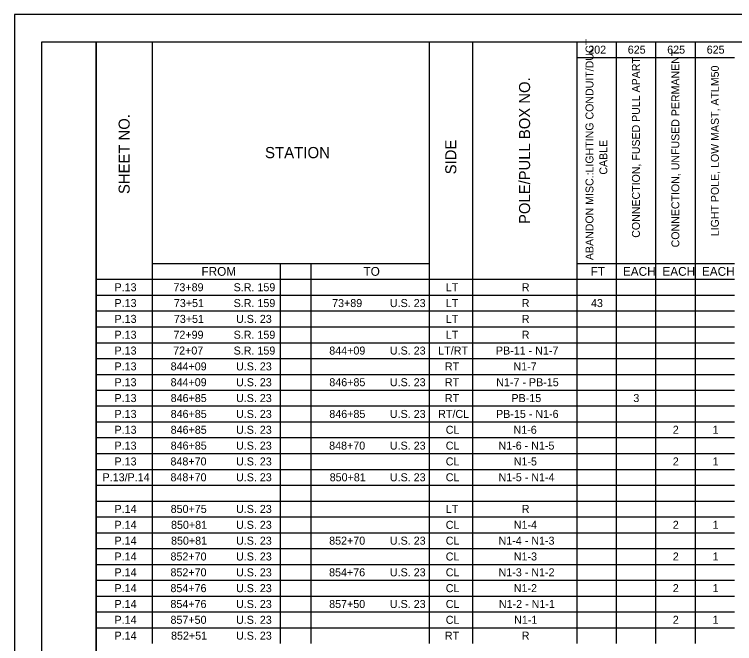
# Model space of a CAD drawing. Extents: x 0 to 34, y 0 to 22.
# Drawn here: x 0 to 13.2, y 10.47 to 22 of the extents above; entities that cross this region are included whole.
import ezdxf

# ---------------------------------------------------------------- set-up
doc = ezdxf.new("R2010")
doc.units = 0
for name, color, linetype in [('Default', 7, 'Continuous'), ('SH_Border', 7, 'Continuous'), ('SH_Cut_Line', 7, 'Continuous')]:
    doc.layers.add(name, color=color, linetype=linetype)

msp = doc.modelspace()

# ---------------------------------------------------------------- linework, layer by layer
at = {"layer": 'Default'}
for p, q in [((1.5, 21.5), (4.872, 21.5)), ((1.5, 21.5), (1.5, 21.21)), ((2.524, 21.5), (2.524, 21.21)), ((4.872, 21.5), (5.432, 21.5)), ((5.432, 21.5), (13.2, 21.5)), ((7.603, 21.5), (7.603, 21.21)), ((8.394, 21.5), (8.394, 21.21)), ((10.306, 21.5), (10.306, 21.21)), ((11.029, 21.5), (11.029, 21.21)), ((11.753, 21.5), (11.753, 21.21)), ((12.476, 21.5), (12.476, 21.21)), ((1.5, 21.21), (1.5, 20.92)), ((2.524, 21.21), (2.524, 20.92)), ((7.603, 21.21), (7.603, 20.92)), ((8.394, 21.21), (8.394, 20.92)), ((10.306, 21.21), (13.2, 21.21)), ((10.306, 21.21), (10.306, 20.92)), ((11.029, 21.21), (11.029, 20.92)), ((11.753, 21.21), (11.753, 20.92)), ((12.476, 21.21), (12.476, 20.92)), ((1.5, 20.92), (1.5, 20.63)), ((2.524, 20.92), (2.524, 20.63)), ((7.603, 20.92), (7.603, 20.63)), ((8.394, 20.92), (8.394, 20.63)), ((10.306, 20.92), (10.306, 20.63)), ((11.029, 20.92), (11.029, 20.63)), ((11.753, 20.92), (11.753, 20.63)), ((12.476, 20.92), (12.476, 20.63)), ((1.5, 20.63), (1.5, 20.339)), ((2.524, 20.63), (2.524, 20.339)), ((7.603, 20.63), (7.603, 20.339)), ((8.394, 20.63), (8.394, 20.339)), ((10.306, 20.63), (10.306, 20.339)), ((11.029, 20.63), (11.029, 20.339)), ((11.753, 20.63), (11.753, 20.339)), ((12.476, 20.63), (12.476, 20.339)), ((1.5, 20.339), (1.5, 20.049)), ((2.524, 20.339), (2.524, 20.049)), ((7.603, 20.339), (7.603, 20.049)), ((8.394, 20.339), (8.394, 20.049)), ((10.306, 20.339), (10.306, 20.049)), ((11.029, 20.339), (11.029, 20.049)), ((11.753, 20.339), (11.753, 20.049)), ((12.476, 20.339), (12.476, 20.049)), ((1.5, 20.049), (1.5, 19.759)), ((2.524, 20.049), (2.524, 19.759)), ((7.603, 20.049), (7.603, 19.759)), ((8.394, 20.049), (8.394, 19.759)), ((10.306, 20.049), (10.306, 19.759)), ((11.029, 20.049), (11.029, 19.759)), ((11.753, 20.049), (11.753, 19.759)), ((12.476, 20.049), (12.476, 19.759)), ((1.5, 19.759), (1.5, 19.469)), ((2.524, 19.759), (2.524, 19.469)), ((7.603, 19.759), (7.603, 19.469)), ((8.394, 19.759), (8.394, 19.469)), ((10.306, 19.759), (10.306, 19.469)), ((11.029, 19.759), (11.029, 19.469)), ((11.753, 19.759), (11.753, 19.469)), ((12.476, 19.759), (12.476, 19.469)), ((1.5, 19.469), (1.5, 19.179)), ((2.524, 19.469), (2.524, 19.179)), ((7.603, 19.469), (7.603, 19.179)), ((8.394, 19.469), (8.394, 19.179)), ((10.306, 19.469), (10.306, 19.179)), ((11.029, 19.469), (11.029, 19.179)), ((11.753, 19.469), (11.753, 19.179)), ((12.476, 19.469), (12.476, 19.179)), ((1.5, 19.179), (1.5, 18.889)), ((2.524, 19.179), (2.524, 18.889)), ((7.603, 19.179), (7.603, 18.889)), ((8.394, 19.179), (8.394, 18.889)), ((10.306, 19.179), (10.306, 18.889)), ((11.029, 19.179), (11.029, 18.889)), ((11.753, 19.179), (11.753, 18.889)), ((12.476, 19.179), (12.476, 18.889)), ((1.5, 18.889), (1.5, 18.599)), ((2.524, 18.889), (2.524, 18.599)), ((7.603, 18.889), (7.603, 18.599)), ((8.394, 18.889), (8.394, 18.599)), ((10.306, 18.889), (10.306, 18.599)), ((11.029, 18.889), (11.029, 18.599)), ((11.753, 18.889), (11.753, 18.599)), ((12.476, 18.889), (12.476, 18.599)), ((1.5, 18.599), (1.5, 18.308)), ((2.524, 18.599), (2.524, 18.308)), ((7.603, 18.599), (7.603, 18.308)), ((8.394, 18.599), (8.394, 18.308)), ((10.306, 18.599), (10.306, 18.308)), ((11.029, 18.599), (11.029, 18.308)), ((11.753, 18.599), (11.753, 18.308)), ((12.476, 18.599), (12.476, 18.308)), ((1.5, 18.308), (1.5, 18.018)), ((2.524, 18.308), (2.524, 18.018)), ((7.603, 18.308), (7.603, 18.018)), ((8.394, 18.308), (8.394, 18.018)), ((10.306, 18.308), (10.306, 18.018)), ((11.029, 18.308), (11.029, 18.018)), ((11.753, 18.308), (11.753, 18.018)), ((12.476, 18.308), (12.476, 18.018)), ((1.5, 18.018), (1.5, 17.728)), ((2.524, 18.018), (2.524, 17.728)), ((7.603, 18.018), (7.603, 17.728)), ((8.394, 18.018), (8.394, 17.728)), ((10.306, 18.018), (10.306, 17.728)), ((11.029, 18.018), (11.029, 17.728)), ((11.753, 18.018), (11.753, 17.728)), ((12.476, 18.018), (12.476, 17.728)), ((1.5, 17.728), (1.5, 17.438)), ((2.524, 17.728), (2.524, 17.438)), ((7.603, 17.728), (7.603, 17.438)), ((8.394, 17.728), (8.394, 17.438)), ((10.306, 17.728), (10.306, 17.438)), ((11.029, 17.728), (11.029, 17.438)), ((11.753, 17.728), (11.753, 17.438)), ((12.476, 17.728), (12.476, 17.438)), ((1.5, 17.438), (1.5, 17.148)), ((2.524, 17.438), (4.872, 17.438)), ((2.524, 17.438), (2.524, 17.148)), ((4.872, 17.438), (5.432, 17.438)), ((4.872, 17.438), (4.872, 17.148)), ((5.432, 17.438), (7.603, 17.438)), ((5.432, 17.438), (5.432, 17.148)), ((7.603, 17.438), (7.603, 17.148)), ((8.394, 17.438), (8.394, 17.148)), ((10.306, 17.438), (13.2, 17.438)), ((10.306, 17.438), (10.306, 17.148)), ((11.029, 17.438), (11.029, 17.148)), ((11.753, 17.438), (11.753, 17.148)), ((12.476, 17.438), (12.476, 17.148)), ((1.5, 17.148), (4.872, 17.148)), ((1.5, 17.148), (1.5, 16.858)), ((2.524, 17.148), (2.524, 16.858)), ((4.872, 17.148), (5.432, 17.148)), ((4.872, 17.148), (4.872, 16.858)), ((5.432, 17.148), (13.2, 17.148)), ((5.432, 17.148), (5.432, 16.858)), ((7.603, 17.148), (7.603, 16.858)), ((8.394, 17.148), (8.394, 16.858)), ((10.306, 17.148), (10.306, 16.858)), ((11.029, 17.148), (11.029, 16.858)), ((11.753, 17.148), (11.753, 16.858)), ((12.476, 17.148), (12.476, 16.858)), ((1.5, 16.858), (4.872, 16.858)), ((1.5, 16.858), (1.5, 16.568)), ((2.524, 16.858), (2.524, 16.568)), ((4.872, 16.858), (5.432, 16.858)), ((4.872, 16.858), (4.872, 16.568)), ((5.432, 16.858), (13.2, 16.858)), ((5.432, 16.858), (5.432, 16.568)), ((7.603, 16.858), (7.603, 16.568)), ((8.394, 16.858), (8.394, 16.568)), ((10.306, 16.858), (10.306, 16.568)), ((11.029, 16.858), (11.029, 16.568)), ((11.753, 16.858), (11.753, 16.568)), ((12.476, 16.858), (12.476, 16.568)), ((1.5, 16.568), (4.872, 16.568)), ((1.5, 16.568), (1.5, 16.278)), ((2.524, 16.568), (2.524, 16.278)), ((4.872, 16.568), (5.432, 16.568)), ((4.872, 16.568), (4.872, 16.278)), ((5.432, 16.568), (13.2, 16.568)), ((5.432, 16.568), (5.432, 16.278)), ((7.603, 16.568), (7.603, 16.278)), ((8.394, 16.568), (8.394, 16.278)), ((10.306, 16.568), (10.306, 16.278)), ((11.029, 16.568), (11.029, 16.278)), ((11.753, 16.568), (11.753, 16.278)), ((12.476, 16.568), (12.476, 16.278)), ((1.5, 16.278), (4.872, 16.278)), ((1.5, 16.278), (1.5, 15.987)), ((2.524, 16.278), (2.524, 15.987)), ((4.872, 16.278), (5.432, 16.278)), ((4.872, 16.278), (4.872, 15.987)), ((5.432, 16.278), (13.2, 16.278)), ((5.432, 16.278), (5.432, 15.987)), ((7.603, 16.278), (7.603, 15.987)), ((8.394, 16.278), (8.394, 15.987)), ((10.306, 16.278), (10.306, 15.987)), ((11.029, 16.278), (11.029, 15.987)), ((11.753, 16.278), (11.753, 15.987)), ((12.476, 16.278), (12.476, 15.987)), ((1.5, 15.987), (4.872, 15.987)), ((1.5, 15.987), (1.5, 15.697)), ((2.524, 15.987), (2.524, 15.697)), ((4.872, 15.987), (5.432, 15.987)), ((4.872, 15.987), (4.872, 15.697)), ((5.432, 15.987), (13.2, 15.987)), ((5.432, 15.987), (5.432, 15.697)), ((7.603, 15.987), (7.603, 15.697)), ((8.394, 15.987), (8.394, 15.697)), ((10.306, 15.987), (10.306, 15.697)), ((11.029, 15.987), (11.029, 15.697)), ((11.753, 15.987), (11.753, 15.697)), ((12.476, 15.987), (12.476, 15.697)), ((1.5, 15.697), (4.872, 15.697)), ((1.5, 15.697), (1.5, 15.407)), ((2.524, 15.697), (2.524, 15.407)), ((4.872, 15.697), (5.432, 15.697)), ((4.872, 15.697), (4.872, 15.407)), ((5.432, 15.697), (13.2, 15.697)), ((5.432, 15.697), (5.432, 15.407)), ((7.603, 15.697), (7.603, 15.407)), ((8.394, 15.697), (8.394, 15.407)), ((10.306, 15.697), (10.306, 15.407)), ((11.029, 15.697), (11.029, 15.407)), ((11.753, 15.697), (11.753, 15.407)), ((12.476, 15.697), (12.476, 15.407)), ((1.5, 15.407), (4.872, 15.407)), ((1.5, 15.407), (1.5, 15.117)), ((2.524, 15.407), (2.524, 15.117)), ((4.872, 15.407), (5.432, 15.407)), ((4.872, 15.407), (4.872, 15.117)), ((5.432, 15.407), (13.2, 15.407)), ((5.432, 15.407), (5.432, 15.117)), ((7.603, 15.407), (7.603, 15.117)), ((8.394, 15.407), (8.394, 15.117)), ((10.306, 15.407), (10.306, 15.117)), ((11.029, 15.407), (11.029, 15.117)), ((11.753, 15.407), (11.753, 15.117)), ((12.476, 15.407), (12.476, 15.117)), ((1.5, 15.117), (4.872, 15.117)), ((1.5, 15.117), (1.5, 14.827)), ((2.524, 15.117), (2.524, 14.827)), ((4.872, 15.117), (5.432, 15.117)), ((4.872, 15.117), (4.872, 14.827)), ((5.432, 15.117), (13.2, 15.117)), ((5.432, 15.117), (5.432, 14.827)), ((7.603, 15.117), (7.603, 14.827)), ((8.394, 15.117), (8.394, 14.827)), ((10.306, 15.117), (10.306, 14.827)), ((11.029, 15.117), (11.029, 14.827)), ((11.753, 15.117), (11.753, 14.827)), ((12.476, 15.117), (12.476, 14.827)), ((1.5, 14.827), (4.872, 14.827)), ((1.5, 14.827), (1.5, 14.537)), ((2.524, 14.827), (2.524, 14.537)), ((4.872, 14.827), (5.432, 14.827)), ((4.872, 14.827), (4.872, 14.537)), ((5.432, 14.827), (13.2, 14.827)), ((5.432, 14.827), (5.432, 14.537)), ((7.603, 14.827), (7.603, 14.537)), ((8.394, 14.827), (8.394, 14.537)), ((10.306, 14.827), (10.306, 14.537)), ((11.029, 14.827), (11.029, 14.537)), ((11.753, 14.827), (11.753, 14.537)), ((12.476, 14.827), (12.476, 14.537)), ((1.5, 14.537), (4.872, 14.537)), ((1.5, 14.537), (1.5, 14.247)), ((2.524, 14.537), (2.524, 14.247)), ((4.872, 14.537), (5.432, 14.537)), ((4.872, 14.537), (4.872, 14.247)), ((5.432, 14.537), (13.2, 14.537)), ((5.432, 14.537), (5.432, 14.247)), ((7.603, 14.537), (7.603, 14.247)), ((8.394, 14.537), (8.394, 14.247)), ((10.306, 14.537), (10.306, 14.247)), ((11.029, 14.537), (11.029, 14.247)), ((11.753, 14.537), (11.753, 14.247)), ((12.476, 14.537), (12.476, 14.247)), ((1.5, 14.247), (4.872, 14.247)), ((1.5, 14.247), (1.5, 13.956)), ((2.524, 14.247), (2.524, 13.956)), ((4.872, 14.247), (5.432, 14.247)), ((4.872, 14.247), (4.872, 13.956)), ((5.432, 14.247), (13.2, 14.247)), ((5.432, 14.247), (5.432, 13.956)), ((7.603, 14.247), (7.603, 13.956)), ((8.394, 14.247), (8.394, 13.956)), ((10.306, 14.247), (10.306, 13.956)), ((11.029, 14.247), (11.029, 13.956)), ((11.753, 14.247), (11.753, 13.956)), ((12.476, 14.247), (12.476, 13.956)), ((1.5, 13.956), (4.872, 13.956)), ((1.5, 13.956), (1.5, 13.666)), ((2.524, 13.956), (2.524, 13.666)), ((4.872, 13.956), (5.432, 13.956)), ((4.872, 13.956), (4.872, 13.666)), ((5.432, 13.956), (13.2, 13.956)), ((5.432, 13.956), (5.432, 13.666)), ((7.603, 13.956), (7.603, 13.666)), ((8.394, 13.956), (8.394, 13.666)), ((10.306, 13.956), (10.306, 13.666)), ((11.029, 13.956), (11.029, 13.666)), ((11.753, 13.956), (11.753, 13.666)), ((12.476, 13.956), (12.476, 13.666)), ((1.5, 13.666), (4.872, 13.666)), ((1.5, 13.666), (1.5, 13.376)), ((2.524, 13.666), (2.524, 13.376)), ((4.872, 13.666), (5.432, 13.666)), ((4.872, 13.666), (4.872, 13.376)), ((5.432, 13.666), (13.2, 13.666)), ((5.432, 13.666), (5.432, 13.376)), ((7.603, 13.666), (7.603, 13.376)), ((8.394, 13.666), (8.394, 13.376)), ((10.306, 13.666), (10.306, 13.376)), ((11.029, 13.666), (11.029, 13.376)), ((11.753, 13.666), (11.753, 13.376)), ((12.476, 13.666), (12.476, 13.376)), ((1.5, 13.376), (4.872, 13.376)), ((1.5, 13.376), (1.5, 13.086)), ((2.524, 13.376), (2.524, 13.086)), ((4.872, 13.376), (5.432, 13.376)), ((4.872, 13.376), (4.872, 13.086)), ((5.432, 13.376), (13.2, 13.376)), ((5.432, 13.376), (5.432, 13.086)), ((7.603, 13.376), (7.603, 13.086)), ((8.394, 13.376), (8.394, 13.086)), ((10.306, 13.376), (10.306, 13.086)), ((11.029, 13.376), (11.029, 13.086)), ((11.753, 13.376), (11.753, 13.086)), ((12.476, 13.376), (12.476, 13.086)), ((1.5, 13.086), (4.872, 13.086)), ((1.5, 13.086), (1.5, 12.796)), ((2.524, 13.086), (2.524, 12.796)), ((4.872, 13.086), (5.432, 13.086)), ((4.872, 13.086), (4.872, 12.796)), ((5.432, 13.086), (13.2, 13.086)), ((5.432, 13.086), (5.432, 12.796)), ((7.603, 13.086), (7.603, 12.796)), ((8.394, 13.086), (8.394, 12.796)), ((10.306, 13.086), (10.306, 12.796)), ((11.029, 13.086), (11.029, 12.796)), ((11.753, 13.086), (11.753, 12.796)), ((12.476, 13.086), (12.476, 12.796)), ((1.5, 12.796), (4.872, 12.796)), ((1.5, 12.796), (1.5, 12.506)), ((2.524, 12.796), (2.524, 12.506)), ((4.872, 12.796), (5.432, 12.796)), ((4.872, 12.796), (4.872, 12.506)), ((5.432, 12.796), (13.2, 12.796)), ((5.432, 12.796), (5.432, 12.506)), ((7.603, 12.796), (7.603, 12.506)), ((8.394, 12.796), (8.394, 12.506)), ((10.306, 12.796), (10.306, 12.506)), ((11.029, 12.796), (11.029, 12.506)), ((11.753, 12.796), (11.753, 12.506)), ((12.476, 12.796), (12.476, 12.506)), ((1.5, 12.506), (4.872, 12.506)), ((1.5, 12.506), (1.5, 12.216)), ((2.524, 12.506), (2.524, 12.216)), ((4.872, 12.506), (5.432, 12.506)), ((4.872, 12.506), (4.872, 12.216)), ((5.432, 12.506), (13.2, 12.506)), ((5.432, 12.506), (5.432, 12.216)), ((7.603, 12.506), (7.603, 12.216)), ((8.394, 12.506), (8.394, 12.216)), ((10.306, 12.506), (10.306, 12.216)), ((11.029, 12.506), (11.029, 12.216)), ((11.753, 12.506), (11.753, 12.216)), ((12.476, 12.506), (12.476, 12.216)), ((1.5, 12.216), (4.872, 12.216)), ((1.5, 12.216), (1.5, 11.926)), ((2.524, 12.216), (2.524, 11.926)), ((4.872, 12.216), (5.432, 12.216)), ((4.872, 12.216), (4.872, 11.926)), ((5.432, 12.216), (13.2, 12.216)), ((5.432, 12.216), (5.432, 11.926)), ((7.603, 12.216), (7.603, 11.926)), ((8.394, 12.216), (8.394, 11.926)), ((10.306, 12.216), (10.306, 11.926)), ((11.029, 12.216), (11.029, 11.926)), ((11.753, 12.216), (11.753, 11.926)), ((12.476, 12.216), (12.476, 11.926)), ((1.5, 11.926), (4.872, 11.926)), ((1.5, 11.926), (1.5, 11.635)), ((2.524, 11.926), (2.524, 11.635)), ((4.872, 11.926), (5.432, 11.926)), ((4.872, 11.926), (4.872, 11.635)), ((5.432, 11.926), (13.2, 11.926)), ((5.432, 11.926), (5.432, 11.635)), ((7.603, 11.926), (7.603, 11.635)), ((8.394, 11.926), (8.394, 11.635)), ((10.306, 11.926), (10.306, 11.635)), ((11.029, 11.926), (11.029, 11.635)), ((11.753, 11.926), (11.753, 11.635)), ((12.476, 11.926), (12.476, 11.635)), ((1.5, 11.635), (4.872, 11.635)), ((1.5, 11.635), (1.5, 11.345)), ((2.524, 11.635), (2.524, 11.345)), ((4.872, 11.635), (5.432, 11.635)), ((4.872, 11.635), (4.872, 11.345)), ((5.432, 11.635), (13.2, 11.635)), ((5.432, 11.635), (5.432, 11.345)), ((7.603, 11.635), (7.603, 11.345)), ((8.394, 11.635), (8.394, 11.345)), ((10.306, 11.635), (10.306, 11.345)), ((11.029, 11.635), (11.029, 11.345)), ((11.753, 11.635), (11.753, 11.345)), ((12.476, 11.635), (12.476, 11.345)), ((1.5, 11.345), (4.872, 11.345)), ((1.5, 11.345), (1.5, 11.055)), ((2.524, 11.345), (2.524, 11.055)), ((4.872, 11.345), (5.432, 11.345)), ((4.872, 11.345), (4.872, 11.055)), ((5.432, 11.345), (13.2, 11.345)), ((5.432, 11.345), (5.432, 11.055)), ((7.603, 11.345), (7.603, 11.055)), ((8.394, 11.345), (8.394, 11.055)), ((10.306, 11.345), (10.306, 11.055)), ((11.029, 11.345), (11.029, 11.055)), ((11.753, 11.345), (11.753, 11.055)), ((12.476, 11.345), (12.476, 11.055)), ((1.5, 11.055), (4.872, 11.055)), ((1.5, 11.055), (1.5, 10.765)), ((2.524, 11.055), (2.524, 10.765)), ((4.872, 11.055), (5.432, 11.055)), ((4.872, 11.055), (4.872, 10.765)), ((5.432, 11.055), (13.2, 11.055)), ((5.432, 11.055), (5.432, 10.765)), ((7.603, 11.055), (7.603, 10.765)), ((8.394, 11.055), (8.394, 10.765)), ((10.306, 11.055), (10.306, 10.765)), ((11.029, 11.055), (11.029, 10.765)), ((11.753, 11.055), (11.753, 10.765)), ((12.476, 11.055), (12.476, 10.765)), ((1.5, 10.765), (4.872, 10.765)), ((1.5, 10.765), (1.5, 10.475)), ((2.524, 10.765), (2.524, 10.475)), ((4.872, 10.765), (5.432, 10.765)), ((4.872, 10.765), (4.872, 10.475)), ((5.432, 10.765), (13.2, 10.765)), ((5.432, 10.765), (5.432, 10.475)), ((7.603, 10.765), (7.603, 10.475)), ((8.394, 10.765), (8.394, 10.475)), ((10.306, 10.765), (10.306, 10.475)), ((11.029, 10.765), (11.029, 10.475)), ((11.753, 10.765), (11.753, 10.475)), ((12.476, 10.765), (12.476, 10.475))]:
    msp.add_line(p, q, dxfattribs=at)
at = {"layer": 'SH_Border'}
for points in [[(0.5, 21.5), (1.5, 21.5), (1.5, 0.5), (0.5, 0.5)], [(1.5, 21.5), (33.5, 21.5), (33.5, 0.5), (1.5, 0.5)]]:
    msp.add_lwpolyline(points, close=True, dxfattribs=at)
at = {"layer": 'SH_Cut_Line'}
msp.add_lwpolyline([(0, 0), (34, 0), (34, 22), (0, 22)], close=True, dxfattribs=at)

# ---------------------------------------------------------------- texts
at = {"layer": 'Default'}
for s, height, p in [('ABANDON MISC.:LIGHTING CONDUIT/DUCT ', 0.14506, (10.613, 17.499)), ('CONNECTION, UNFUSED PERMANENT', 0.14506, (12.187, 17.733)), ('CONNECTION, FUSED PULL APART', 0.14506, (11.464, 17.909)), ('LIGHT POLE, LOW MAST, ATLM50', 0.14506, (12.911, 17.937)), ('POLE/PULL BOX NO.', 0.20308, (9.452, 18.161)), ('SHEET NO.', 0.2031, (2.113, 18.71)), ('SIDE', 0.2031, (8.1, 19.071)), ('CABLE', 0.1451, (10.867, 19.065))]:
    msp.add_text(s, height=height, rotation=90, dxfattribs=at).set_placement(p)
for s, height, p in [('202', 0.1468, (10.518, 21.281)), ('625', 0.1468, (11.242, 21.281)), ('625', 0.1468, (11.965, 21.281)), ('625', 0.1468, (12.689, 21.281)), ('STATION', 0.2055, (4.593, 19.366)), ('FROM', 0.1615, (3.428, 17.212)), ('TO', 0.1615, (6.398, 17.212)), ('FT', 0.1615, (10.562, 17.212)), ('EACH', 0.1615, (11.153, 17.212)), ('EACH', 0.1615, (11.877, 17.212)), ('EACH', 0.1615, (12.601, 17.212)), ('P.13', 0.1468, (1.835, 16.929)), ('73+89', 0.1468, (2.915, 16.929)), ('S.R. 159', 0.1468, (4.018, 16.929)), ('LT', 0.1468, (7.907, 16.929)), ('R', 0.147, (9.299, 16.929)), ('P.13', 0.1468, (1.835, 16.639)), ('73+51', 0.1468, (2.923, 16.639)), ('S.R. 159', 0.1468, (4.018, 16.639)), ('73+89', 0.1468, (5.823, 16.639)), ('U.S. 23', 0.1468, (6.882, 16.639)), ('LT', 0.1468, (7.907, 16.639)), ('R', 0.147, (9.299, 16.639)), ('43', 0.1468, (10.568, 16.639)), ('P.13', 0.1468, (1.835, 16.349)), ('73+51', 0.1468, (2.923, 16.349)), ('U.S. 23', 0.1468, (4.062, 16.349)), ('LT', 0.1468, (7.907, 16.349)), ('R', 0.147, (9.299, 16.349)), ('P.13', 0.1468, (1.835, 16.059)), ('72+99', 0.1468, (2.915, 16.059)), ('S.R. 159', 0.1468, (4.018, 16.059)), ('LT', 0.1468, (7.907, 16.059)), ('R', 0.147, (9.299, 16.059)), ('P.13', 0.1468, (1.835, 15.769)), ('72+07', 0.1468, (2.91, 15.769)), ('S.R. 159', 0.1468, (4.018, 15.769)), ('844+09', 0.1468, (5.771, 15.769)), ('U.S. 23', 0.1468, (6.882, 15.769)), ('LT/RT', 0.1468, (7.768, 15.769)), ('PB-11 - N1-7', 0.14679, (8.825, 15.769)), ('P.13', 0.1468, (1.835, 15.479)), ('844+09', 0.1468, (2.863, 15.479)), ('U.S. 23', 0.1468, (4.062, 15.479)), ('RT', 0.1468, (7.89, 15.479)), ('N1-7', 0.1468, (9.146, 15.479)), ('P.13', 0.1468, (1.835, 15.189)), ('844+09', 0.1468, (2.863, 15.189)), ('U.S. 23', 0.1468, (4.062, 15.189)), ('846+85', 0.1468, (5.772, 15.189)), ('U.S. 23', 0.1468, (6.882, 15.189)), ('RT', 0.1468, (7.89, 15.189)), ('N1-7 - PB-15', 0.14679, (8.831, 15.189)), ('P.13', 0.1468, (1.835, 14.899)), ('846+85', 0.1468, (2.864, 14.899)), ('U.S. 23', 0.1468, (4.062, 14.899)), ('RT', 0.1468, (7.89, 14.899)), ('PB-15', 0.1468, (9.11, 14.899)), ('3', 0.147, (11.344, 14.899)), ('P.13', 0.1468, (1.835, 14.608)), ('846+85', 0.1468, (2.864, 14.608)), ('U.S. 23', 0.1468, (4.062, 14.608)), ('846+85', 0.1468, (5.772, 14.608)), ('U.S. 23', 0.1468, (6.882, 14.608)), ('RT/CL', 0.1468, (7.767, 14.608)), ('PB-15 - N1-6', 0.14679, (8.828, 14.608)), ('P.13', 0.1468, (1.835, 14.318)), ('846+85', 0.1468, (2.864, 14.318)), ('U.S. 23', 0.1468, (4.062, 14.318)), ('CL', 0.1468, (7.906, 14.318)), ('N1-6', 0.1468, (9.148, 14.318)), ('2', 0.147, (12.067, 14.318)), ('1', 0.147, (12.796, 14.318)), ('P.13', 0.1468, (1.835, 14.028)), ('846+85', 0.1468, (2.864, 14.028)), ('U.S. 23', 0.1468, (4.062, 14.028)), ('848+70', 0.1468, (5.769, 14.028)), ('U.S. 23', 0.1468, (6.882, 14.028)), ('CL', 0.1468, (7.906, 14.028)), ('N1-6 - N1-5', 0.14679, (8.872, 14.028)), ('P.13', 0.1468, (1.835, 13.738)), ('848+70', 0.1468, (2.861, 13.738)), ('U.S. 23', 0.1468, (4.062, 13.738)), ('CL', 0.1468, (7.906, 13.738)), ('N1-5', 0.1468, (9.152, 13.738)), ('2', 0.147, (12.067, 13.738)), ('1', 0.147, (12.796, 13.738)), ('P.13/P.14', 0.1468, (1.616, 13.448)), ('848+70', 0.1468, (2.861, 13.448)), ('U.S. 23', 0.1468, (4.062, 13.448)), ('850+81', 0.1468, (5.779, 13.448)), ('U.S. 23', 0.1468, (6.882, 13.448)), ('CL', 0.1468, (7.906, 13.448)), ('N1-5 - N1-4', 0.14679, (8.874, 13.448)), ('P.14', 0.1468, (1.835, 12.868)), ('850+75', 0.1468, (2.864, 12.868)), ('U.S. 23', 0.1468, (4.062, 12.868)), ('LT', 0.1468, (7.907, 12.868)), ('R', 0.147, (9.299, 12.868)), ('P.14', 0.1468, (1.835, 12.577)), ('850+81', 0.1468, (2.871, 12.577)), ('U.S. 23', 0.1468, (4.062, 12.577)), ('CL', 0.1468, (7.906, 12.577)), ('N1-4', 0.1468, (9.153, 12.577)), ('2', 0.147, (12.067, 12.577)), ('1', 0.147, (12.796, 12.577)), ('P.14', 0.1468, (1.835, 12.287)), ('850+81', 0.1468, (2.871, 12.287)), ('U.S. 23', 0.1468, (4.062, 12.287)), ('852+70', 0.1468, (5.769, 12.287)), ('U.S. 23', 0.1468, (6.882, 12.287)), ('CL', 0.1468, (7.906, 12.287)), ('N1-4 - N1-3', 0.14679, (8.874, 12.287)), ('852+70', 0.1468, (2.861, 11.997)), ('U.S. 23', 0.1468, (4.062, 11.997)), ('CL', 0.1468, (7.906, 11.997)), ('N1-3', 0.1468, (9.153, 11.997)), ('2', 0.147, (12.067, 11.997)), ('P.14', 0.1468, (1.835, 11.997)), ('1', 0.147, (12.796, 11.997)), ('P.14', 0.1468, (1.835, 11.707)), ('852+70', 0.1468, (2.861, 11.707)), ('U.S. 23', 0.1468, (4.062, 11.707)), ('854+76', 0.1468, (5.768, 11.707)), ('U.S. 23', 0.1468, (6.882, 11.707)), ('CL', 0.1468, (7.906, 11.707)), ('N1-3 - N1-2', 0.14679, (8.874, 11.707)), ('P.14', 0.1468, (1.835, 11.417)), ('854+76', 0.1468, (2.86, 11.417)), ('U.S. 23', 0.1468, (4.062, 11.417)), ('CL', 0.1468, (7.906, 11.417)), ('N1-2', 0.1468, (9.153, 11.417)), ('2', 0.147, (12.067, 11.417)), ('1', 0.147, (12.796, 11.417)), ('P.14', 0.1468, (1.835, 11.127)), ('854+76', 0.1468, (2.86, 11.127)), ('U.S. 23', 0.1468, (4.062, 11.127)), ('857+50', 0.1468, (5.769, 11.127)), ('U.S. 23', 0.1468, (6.882, 11.127)), ('CL', 0.1468, (7.906, 11.127)), ('N1-2 - N1-1', 0.14679, (8.88, 11.127)), ('P.14', 0.1468, (1.835, 10.837)), ('857+50', 0.1468, (2.861, 10.837)), ('U.S. 23', 0.1468, (4.062, 10.837)), ('CL', 0.1468, (7.906, 10.837)), ('N1-1', 0.1468, (9.159, 10.837)), ('2', 0.147, (12.067, 10.837)), ('1', 0.147, (12.796, 10.837)), ('P.14', 0.1468, (1.835, 10.547)), ('852+51', 0.1468, (2.871, 10.547)), ('U.S. 23', 0.1468, (4.062, 10.547)), ('RT', 0.1468, (7.89, 10.547)), ('R', 0.147, (9.299, 10.547))]:
    msp.add_text(s, height=height, dxfattribs=at).set_placement(p)

doc.saveas('drawing.dxf')
